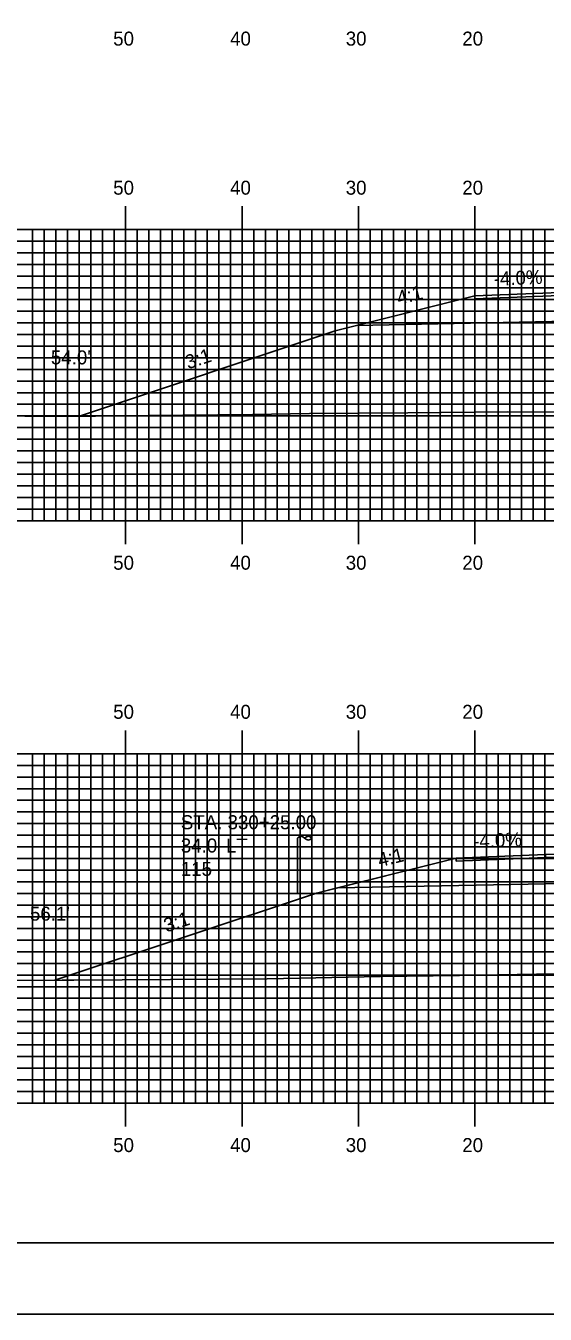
# Model space of a CAD drawing. Extents: x 1822392 to 1822735, y 442591 to 442811.
# Drawn here: x 1822499.2 to 1822543.8, y 442590.5 to 442701.2 of the extents above; entities that cross this region are included whole.
import ezdxf

# ---------------------------------------------------------------- set-up
doc = ezdxf.new("R2010")
doc.units = 0
for name, color, linetype in [('ANNOTATION', 7, 'Continuous'), ('BORDER', 7, 'Continuous'), ('D_Drainage_Text', 7, 'Continuous'), ('D_Roadway_Centerline', 7, 'Continuous'), ('D_Roadway_Edge_Shoulder', 7, 'Continuous'), ('D_Roadway_SlopeLines', 7, 'Continuous'), ('D_Roadway_SubGrade', 7, 'Continuous'), ('D_Text_Standard', 7, 'Continuous'), ('D_Utilities_Pole_Joint', 7, 'Continuous'), ('H_V ANNOTATION', 7, 'Continuous'), ('MAJOR', 7, 'Continuous'), ('MINOR', 7, 'Continuous'), ('PLOT BOUNDARY', 7, 'Continuous'), ('S_Roadway_Centerline', 7, 'Continuous')]:
    doc.layers.add(name, color=color, linetype=linetype)

msp = doc.modelspace()

# ---------------------------------------------------------------- linework, layer by layer
at = {"layer": 'BORDER'}
msp.add_lwpolyline([(1822408.17, 442596.67), (1822728.17, 442596.67), (1822728.17, 442806.67), (1822408.17, 442806.67)], close=True, dxfattribs=at)
at = {"layer": 'D_Roadway_Centerline'}
for points in [[(1822503.81, 442667.66), (1822525.77, 442674.98), (1822527.6, 442675.44), (1822537.77, 442677.98), (1822545.77, 442678.3), (1822557.77, 442678.54), (1822569.77, 442678.3), (1822577.77, 442677.98), (1822587.94, 442675.44), (1822589.77, 442674.98), (1822609.48, 442668.41)], [(1822501.7, 442619.22), (1822524.16, 442626.7), (1822525.96, 442627.15), (1822536.16, 442629.7), (1822543.84, 442630.01), (1822557.77, 442630.29), (1822569.77, 442630.05), (1822577.77, 442629.73), (1822587.94, 442627.19), (1822589.77, 442626.73), (1822605.93, 442621.34)]]:
    msp.add_lwpolyline(points, dxfattribs=at)
at = {"layer": 'D_Roadway_Edge_Shoulder'}
for points in [[(1822545.77, 442678.3), (1822537.77, 442677.98), (1822537.77, 442677.73), (1822545.77, 442678.05)], [(1822543.84, 442630.01), (1822536.16, 442629.7), (1822536.16, 442629.45), (1822543.84, 442629.76)]]:
    msp.add_lwpolyline(points, close=True, dxfattribs=at)
at = {"layer": 'D_Roadway_SlopeLines'}
for points in [[(1822537.77, 442677.98), (1822525.77, 442674.98), (1822503.81, 442667.66)], [(1822536.16, 442629.7), (1822524.16, 442626.7), (1822501.7, 442619.22)]]:
    msp.add_lwpolyline(points, dxfattribs=at)
at = {"layer": 'D_Roadway_SubGrade'}
for points in [[(1822545.77, 442675.8), (1822527.6, 442675.44), (1822537.77, 442677.98), (1822537.77, 442677.73), (1822545.77, 442678.05), (1822557.77, 442678.29), (1822569.77, 442678.05), (1822577.77, 442677.73), (1822577.77, 442677.98), (1822587.94, 442675.44), (1822569.77, 442675.8), (1822557.77, 442676.04)], [(1822543.84, 442627.51), (1822525.96, 442627.15), (1822536.16, 442629.7), (1822536.16, 442629.45), (1822543.84, 442629.76), (1822557.77, 442630.04), (1822569.77, 442629.8), (1822577.77, 442629.48), (1822577.77, 442629.73), (1822587.94, 442627.19), (1822569.77, 442627.55), (1822557.77, 442627.79)]]:
    msp.add_lwpolyline(points, close=True, dxfattribs=at)
at = {"layer": 'D_Utilities_Pole_Joint'}
for p, q in [((1822522.52, 442631.42), (1822522.68, 442631.53)), ((1822522.99, 442631.53), (1822523.14, 442631.42)), ((1822523.3, 442631.53), (1822523.14, 442631.42)), ((1822523.77, 442631.42), (1822523.61, 442631.53)), ((1822522.52, 442626.67), (1822522.52, 442631.42)), ((1822523.14, 442631.42), (1822523.3, 442631.31)), ((1822523.61, 442631.31), (1822523.77, 442631.42)), ((1822523.77, 442626.67), (1822523.77, 442631.42))]:
    msp.add_line(p, q, dxfattribs=at)
for centre, start, end in [((1822522.83, 442631.31), 90, 125.2644), ((1822522.83, 442631.31), 54.7356, 90), ((1822523.46, 442631.31), 90, 125.2644), ((1822523.46, 442631.31), 54.7356, 90), ((1822523.46, 442631.53), 234.7356, 270), ((1822523.46, 442631.53), 270, 305.2644)]:
    msp.add_arc(centre, 0.271, start, end, dxfattribs=at)
at = {"layer": 'MAJOR'}
for p, q in [((1822507.77, 442685.67), (1822507.77, 442683.67)), ((1822517.77, 442685.67), (1822517.77, 442683.67)), ((1822527.77, 442685.67), (1822527.77, 442683.67)), ((1822537.77, 442685.67), (1822537.77, 442683.67)), ((1822417.77, 442683.67), (1822697.77, 442683.67)), ((1822417.77, 442683.67), (1822697.77, 442683.67)), ((1822507.77, 442658.67), (1822507.77, 442683.67)), ((1822517.77, 442658.67), (1822517.77, 442683.67)), ((1822527.77, 442658.67), (1822527.77, 442683.67)), ((1822537.77, 442658.67), (1822537.77, 442683.67)), ((1822417.77, 442678.67), (1822697.77, 442678.67)), ((1822417.77, 442673.67), (1822697.77, 442673.67)), ((1822417.77, 442668.67), (1822697.77, 442668.67)), ((1822417.77, 442663.67), (1822697.77, 442663.67)), ((1822417.77, 442658.67), (1822697.77, 442658.67)), ((1822417.77, 442658.67), (1822697.77, 442658.67)), ((1822507.77, 442656.66), (1822507.77, 442658.67)), ((1822517.77, 442656.66), (1822517.77, 442658.67)), ((1822527.77, 442656.66), (1822527.77, 442658.67)), ((1822537.77, 442656.66), (1822537.77, 442658.67)), ((1822507.77, 442640.67), (1822507.77, 442638.67)), ((1822517.77, 442640.67), (1822517.77, 442638.67)), ((1822527.77, 442640.67), (1822527.77, 442638.67)), ((1822537.77, 442640.67), (1822537.77, 442638.67)), ((1822417.77, 442638.67), (1822697.77, 442638.67)), ((1822417.77, 442638.67), (1822697.77, 442638.67)), ((1822507.77, 442608.67), (1822507.77, 442638.67)), ((1822517.77, 442608.67), (1822517.77, 442638.67)), ((1822527.77, 442608.67), (1822527.77, 442638.67)), ((1822537.77, 442608.67), (1822537.77, 442638.67)), ((1822417.77, 442633.67), (1822697.77, 442633.67)), ((1822417.77, 442628.67), (1822697.77, 442628.67)), ((1822417.77, 442623.67), (1822697.77, 442623.67)), ((1822417.77, 442618.67), (1822697.77, 442618.67)), ((1822417.77, 442613.67), (1822697.77, 442613.67)), ((1822417.77, 442608.67), (1822697.77, 442608.67)), ((1822417.77, 442608.67), (1822697.77, 442608.67)), ((1822507.77, 442606.66), (1822507.77, 442608.67)), ((1822517.77, 442606.66), (1822517.77, 442608.67)), ((1822527.77, 442606.66), (1822527.77, 442608.67)), ((1822537.77, 442606.66), (1822537.77, 442608.67))]:
    msp.add_line(p, q, dxfattribs=at)
at = {"layer": 'MINOR'}
for p, q in [((1822499.77, 442658.67), (1822499.77, 442683.67)), ((1822500.77, 442658.67), (1822500.77, 442683.67)), ((1822501.77, 442658.67), (1822501.77, 442683.67)), ((1822502.77, 442658.67), (1822502.77, 442683.67)), ((1822503.77, 442658.67), (1822503.77, 442683.67)), ((1822504.77, 442658.67), (1822504.77, 442683.67)), ((1822505.77, 442658.67), (1822505.77, 442683.67)), ((1822506.77, 442658.67), (1822506.77, 442683.67)), ((1822508.77, 442658.67), (1822508.77, 442683.67)), ((1822509.77, 442658.67), (1822509.77, 442683.67)), ((1822510.77, 442658.67), (1822510.77, 442683.67)), ((1822511.77, 442658.67), (1822511.77, 442683.67)), ((1822512.77, 442658.67), (1822512.77, 442683.67)), ((1822513.77, 442658.67), (1822513.77, 442683.67)), ((1822514.77, 442658.67), (1822514.77, 442683.67)), ((1822515.77, 442658.67), (1822515.77, 442683.67)), ((1822516.77, 442658.67), (1822516.77, 442683.67)), ((1822518.77, 442658.67), (1822518.77, 442683.67)), ((1822519.77, 442658.67), (1822519.77, 442683.67)), ((1822520.77, 442658.67), (1822520.77, 442683.67)), ((1822521.77, 442658.67), (1822521.77, 442683.67)), ((1822522.77, 442658.67), (1822522.77, 442683.67)), ((1822523.77, 442658.67), (1822523.77, 442683.67)), ((1822524.77, 442658.67), (1822524.77, 442683.67)), ((1822525.77, 442658.67), (1822525.77, 442683.67)), ((1822526.77, 442658.67), (1822526.77, 442683.67)), ((1822528.77, 442658.67), (1822528.77, 442683.67)), ((1822529.77, 442658.67), (1822529.77, 442683.67)), ((1822530.77, 442658.67), (1822530.77, 442683.67)), ((1822531.77, 442658.67), (1822531.77, 442683.67)), ((1822532.77, 442658.67), (1822532.77, 442683.67)), ((1822533.77, 442658.67), (1822533.77, 442683.67)), ((1822534.77, 442658.67), (1822534.77, 442683.67)), ((1822535.77, 442658.67), (1822535.77, 442683.67)), ((1822536.77, 442658.67), (1822536.77, 442683.67)), ((1822538.77, 442658.67), (1822538.77, 442683.67)), ((1822539.77, 442658.67), (1822539.77, 442683.67)), ((1822540.77, 442658.67), (1822540.77, 442683.67)), ((1822541.77, 442658.67), (1822541.77, 442683.67)), ((1822542.77, 442658.67), (1822542.77, 442683.67)), ((1822543.77, 442658.67), (1822543.77, 442683.67)), ((1822417.77, 442682.67), (1822697.77, 442682.67)), ((1822417.77, 442681.67), (1822697.77, 442681.67)), ((1822417.77, 442680.67), (1822697.77, 442680.67)), ((1822417.77, 442679.67), (1822697.77, 442679.67)), ((1822417.77, 442677.67), (1822697.77, 442677.67)), ((1822417.77, 442676.67), (1822697.77, 442676.67)), ((1822417.77, 442675.67), (1822697.77, 442675.67)), ((1822417.77, 442674.67), (1822697.77, 442674.67)), ((1822417.77, 442672.67), (1822697.77, 442672.67)), ((1822417.77, 442671.67), (1822697.77, 442671.67)), ((1822417.77, 442670.67), (1822697.77, 442670.67)), ((1822417.77, 442669.67), (1822697.77, 442669.67)), ((1822417.77, 442667.67), (1822697.77, 442667.67)), ((1822417.77, 442666.67), (1822697.77, 442666.67)), ((1822417.77, 442665.67), (1822697.77, 442665.67)), ((1822417.77, 442664.67), (1822697.77, 442664.67)), ((1822417.77, 442662.67), (1822697.77, 442662.67)), ((1822417.77, 442661.67), (1822697.77, 442661.67)), ((1822417.77, 442660.67), (1822697.77, 442660.67)), ((1822417.77, 442659.67), (1822697.77, 442659.67)), ((1822499.77, 442608.67), (1822499.77, 442638.67)), ((1822500.77, 442608.67), (1822500.77, 442638.67)), ((1822501.77, 442608.67), (1822501.77, 442638.67)), ((1822502.77, 442608.67), (1822502.77, 442638.67)), ((1822503.77, 442608.67), (1822503.77, 442638.67)), ((1822504.77, 442608.67), (1822504.77, 442638.67)), ((1822505.77, 442608.67), (1822505.77, 442638.67)), ((1822506.77, 442608.67), (1822506.77, 442638.67)), ((1822508.77, 442608.67), (1822508.77, 442638.67)), ((1822509.77, 442608.67), (1822509.77, 442638.67)), ((1822510.77, 442608.67), (1822510.77, 442638.67)), ((1822511.77, 442608.67), (1822511.77, 442638.67)), ((1822512.77, 442608.67), (1822512.77, 442638.67)), ((1822513.77, 442608.67), (1822513.77, 442638.67)), ((1822514.77, 442608.67), (1822514.77, 442638.67)), ((1822515.77, 442608.67), (1822515.77, 442638.67)), ((1822516.77, 442608.67), (1822516.77, 442638.67)), ((1822518.77, 442608.67), (1822518.77, 442638.67)), ((1822519.77, 442608.67), (1822519.77, 442638.67)), ((1822520.77, 442608.67), (1822520.77, 442638.67)), ((1822521.77, 442608.67), (1822521.77, 442638.67)), ((1822522.77, 442608.67), (1822522.77, 442638.67)), ((1822523.77, 442608.67), (1822523.77, 442638.67)), ((1822524.77, 442608.67), (1822524.77, 442638.67)), ((1822525.77, 442608.67), (1822525.77, 442638.67)), ((1822526.77, 442608.67), (1822526.77, 442638.67)), ((1822528.77, 442608.67), (1822528.77, 442638.67)), ((1822529.77, 442608.67), (1822529.77, 442638.67)), ((1822530.77, 442608.67), (1822530.77, 442638.67)), ((1822531.77, 442608.67), (1822531.77, 442638.67)), ((1822532.77, 442608.67), (1822532.77, 442638.67)), ((1822533.77, 442608.67), (1822533.77, 442638.67)), ((1822534.77, 442608.67), (1822534.77, 442638.67)), ((1822535.77, 442608.67), (1822535.77, 442638.67)), ((1822536.77, 442608.67), (1822536.77, 442638.67)), ((1822538.77, 442608.67), (1822538.77, 442638.67)), ((1822539.77, 442608.67), (1822539.77, 442638.67)), ((1822540.77, 442608.67), (1822540.77, 442638.67)), ((1822541.77, 442608.67), (1822541.77, 442638.67)), ((1822542.77, 442608.67), (1822542.77, 442638.67)), ((1822543.77, 442608.67), (1822543.77, 442638.67)), ((1822417.77, 442637.67), (1822697.77, 442637.67)), ((1822417.77, 442636.67), (1822697.77, 442636.67)), ((1822417.77, 442635.67), (1822697.77, 442635.67)), ((1822417.77, 442634.67), (1822697.77, 442634.67)), ((1822417.77, 442632.67), (1822697.77, 442632.67)), ((1822417.77, 442631.67), (1822697.77, 442631.67)), ((1822417.77, 442630.67), (1822697.77, 442630.67)), ((1822417.77, 442629.67), (1822697.77, 442629.67)), ((1822417.77, 442627.67), (1822697.77, 442627.67)), ((1822417.77, 442626.67), (1822697.77, 442626.67)), ((1822417.77, 442625.67), (1822697.77, 442625.67)), ((1822417.77, 442624.67), (1822697.77, 442624.67)), ((1822417.77, 442622.67), (1822697.77, 442622.67)), ((1822417.77, 442621.67), (1822697.77, 442621.67)), ((1822417.77, 442620.67), (1822697.77, 442620.67)), ((1822417.77, 442619.67), (1822697.77, 442619.67)), ((1822417.77, 442617.67), (1822697.77, 442617.67)), ((1822417.77, 442616.67), (1822697.77, 442616.67)), ((1822417.77, 442615.67), (1822697.77, 442615.67)), ((1822417.77, 442614.67), (1822697.77, 442614.67)), ((1822417.77, 442612.67), (1822697.77, 442612.67)), ((1822417.77, 442611.67), (1822697.77, 442611.67)), ((1822417.77, 442610.67), (1822697.77, 442610.67)), ((1822417.77, 442609.67), (1822697.77, 442609.67))]:
    msp.add_line(p, q, dxfattribs=at)
at = {"layer": 'PLOT BOUNDARY'}
msp.add_lwpolyline([(1822391.98, 442590.55), (1822731.98, 442590.55), (1822731.98, 442810.55), (1822391.98, 442810.55)], close=True, dxfattribs=at)
at = {"layer": 'S_Roadway_Centerline'}
for points in [[(1822499.1, 442667.66), (1822505.18, 442667.66), (1822506.71, 442667.68), (1822518.67, 442667.81), (1822523.55, 442667.88), (1822532.01, 442667.94), (1822540.55, 442668.02), (1822545.31, 442667.99), (1822557.35, 442667.92), (1822559.14, 442667.94), (1822567.1, 442668.07), (1822572.77, 442668.18), (1822574.2, 442668.16), (1822577.09, 442668.19), (1822591.7, 442668.38), (1822598.94, 442668.35), (1822607.93, 442668.4), (1822623.32, 442668.51)], [(1822489.21, 442619.21), (1822502.32, 442619.22), (1822503.06, 442619.22), (1822503.33, 442619.22), (1822519.93, 442619.35), (1822529.66, 442619.54), (1822536.44, 442619.62), (1822543.04, 442619.73), (1822554.22, 442619.77), (1822556.61, 442619.81), (1822567.44, 442620.27), (1822570.44, 442620.4), (1822571.39, 442620.42), (1822587.8, 442620.85), (1822595, 442621.06), (1822604.77, 442621.3), (1822617.64, 442621.79)]]:
    msp.add_lwpolyline(points, dxfattribs=at)

# ---------------------------------------------------------------- texts
at = {"layer": 'ANNOTATION'}
for s, rotation, p in [('-4.0%', 2.2906, (1822539.4, 442678.85)), ('4:1', 14.0362, (1822531.22, 442677.2)), ('3:1', 18.4348, (1822513.13, 442671.67)), ('-4.0%', 2.2906, (1822537.63, 442630.56)), ('4:1', 14.0362, (1822529.59, 442628.92)), ('3:1', 18.4348, (1822511.27, 442623.31))]:
    msp.add_text(s, height=1.2, rotation=rotation, dxfattribs=at).set_placement(p)
at = {"layer": 'D_Drainage_Text'}
for s, p in [('STA. 330+25.00', (1822512.51, 442632.19)), ("34.0' LT", (1822512.51, 442630.19)), ('115', (1822512.51, 442628.18))]:
    msp.add_text(s, height=1.2, dxfattribs=at).set_placement(p)
at = {"layer": 'D_Text_Standard'}
for s, p in [("54.0'", (1822501.35, 442672.1)), ("56.1'", (1822499.55, 442624.34))]:
    msp.add_text(s, height=1.2, dxfattribs=at).set_placement(p)
at = {"layer": 'H_V ANNOTATION'}
for s, p in [('50', (1822506.7, 442699.47)), ('40', (1822516.74, 442699.47)), ('30', (1822526.67, 442699.47)), ('20', (1822536.68, 442699.47)), ('50', (1822506.7, 442686.67)), ('40', (1822516.74, 442686.67)), ('30', (1822526.67, 442686.67)), ('20', (1822536.68, 442686.67)), ('50', (1822506.7, 442654.47)), ('40', (1822516.74, 442654.47)), ('30', (1822526.67, 442654.47)), ('20', (1822536.68, 442654.47)), ('50', (1822506.7, 442641.67)), ('40', (1822516.74, 442641.67)), ('30', (1822526.67, 442641.67)), ('20', (1822536.68, 442641.67)), ('50', (1822506.7, 442604.47)), ('40', (1822516.74, 442604.47)), ('30', (1822526.67, 442604.47)), ('20', (1822536.68, 442604.47))]:
    msp.add_text(s, height=1.2, dxfattribs=at).set_placement(p)

doc.saveas('drawing.dxf')
